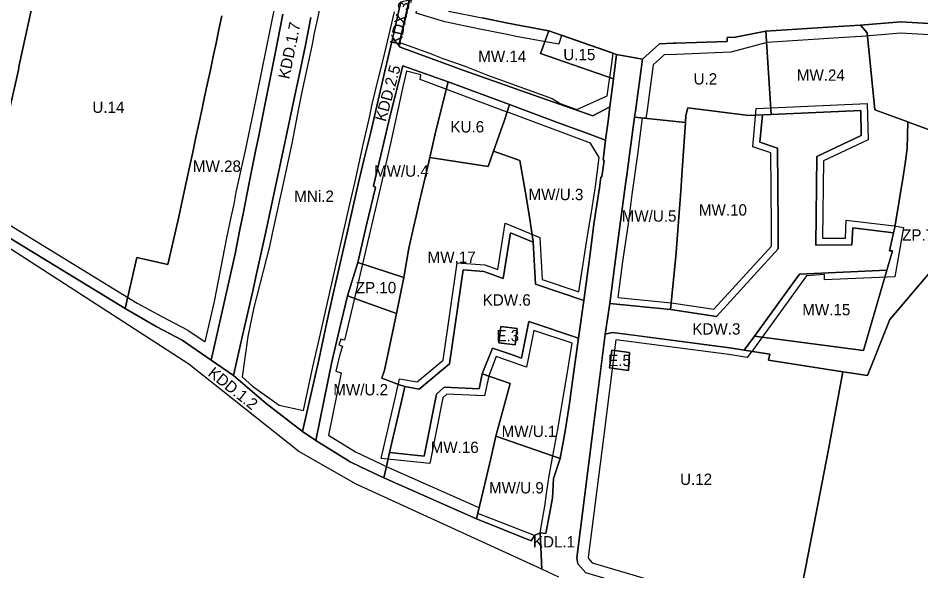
# Model space of a CAD drawing. Extents: x 7421913 to 7423341, y 5550123 to 5551175.
# Drawn here: x 7422221.1 to 7422618.9, y 5550484.1 to 5550727.7 of the extents above; entities that cross this region are included whole.
import ezdxf

# ---------------------------------------------------------------- set-up
doc = ezdxf.new("R2010")
doc.units = 0
for name, color, linetype in [('linie_rozgraniczajace', 7, 'Continuous'), ('linie_zabudowy_nieprzekraczalne', 7, 'Continuous'), ('oznaczenia_przeznaczen', 7, 'Continuous')]:
    doc.layers.add(name, color=color, linetype=linetype)

msp = doc.modelspace()

# ---------------------------------------------------------------- linework, layer by layer
at = {"layer": 'linie_rozgraniczajace'}
for points in [[(7422213.4, 5550774.82), (7422235.34, 5550770.25), (7422234.28, 5550765.52), (7422232.46, 5550757.03), (7422231.35, 5550751.91), (7422231.24, 5550751.35), (7422230.09, 5550746.05), (7422225.78, 5550726.41), (7422221.66, 5550706.89), (7422221.26, 5550704.88), (7422221.11, 5550704.1), (7422217.38, 5550687.41)], [(7422217.38, 5550687.41), (7422221.11, 5550704.1), (7422221.26, 5550704.88), (7422221.66, 5550706.89), (7422225.78, 5550726.41), (7422230.09, 5550746.05)], [(7422389.77, 5550734.83), (7422386.06, 5550718.57), (7422382.76, 5550704.3), (7422376.51, 5550677.37), (7422373.65, 5550665.7), (7422371.09, 5550655.25), (7422366.05, 5550633.02), (7422359.94, 5550606.18), (7422357.09, 5550593.63), (7422353.72, 5550577.68), (7422346.5, 5550545.52), (7422330.37, 5550557.92), (7422316.1, 5550570.15), (7422320.06, 5550587.75), (7422324.64, 5550608.16), (7422325.85, 5550613.68), (7422330.21, 5550633.56), (7422339.26, 5550675.47), (7422343.44, 5550695.67), (7422344.92, 5550702.46), (7422347.79, 5550715.72), (7422350.11, 5550727.89)], [(7422337.8, 5550729.42), (7422336.62, 5550723.39), (7422335.42, 5550717.41), (7422334.23, 5550711.43), (7422333.05, 5550705.55), (7422331.88, 5550699.66), (7422330.71, 5550693.78), (7422329.51, 5550687.8), (7422328.34, 5550681.92), (7422327.12, 5550675.83), (7422325.92, 5550669.86), (7422324.59, 5550663.19), (7422323.26, 5550656.52), (7422321.93, 5550649.85), (7422320.4, 5550642.2), (7422318.88, 5550634.56), (7422316.73, 5550623.77), (7422306.14, 5550576.99), (7422293.48, 5550585.69), (7422282.02, 5550591.84), (7422268.25, 5550599.78), (7422273.44, 5550622.18), (7422287.09, 5550619.14), (7422291.99, 5550640.16), (7422293.62, 5550647.79), (7422295.23, 5550655.31), (7422296.65, 5550661.97), (7422298.08, 5550668.67), (7422299.49, 5550675.26), (7422300.75, 5550681.14), (7422302.03, 5550687.09), (7422303.3, 5550693.05), (7422304.58, 5550699.03), (7422305.83, 5550704.89), (7422307.08, 5550710.77), (7422308.33, 5550716.62), (7422309.63, 5550722.69), (7422310.91, 5550728.65)], [(7422350.11, 5550727.89), (7422347.79, 5550715.72), (7422344.92, 5550702.46), (7422343.44, 5550695.67), (7422339.26, 5550675.47), (7422330.21, 5550633.56), (7422325.85, 5550613.68), (7422324.64, 5550608.16), (7422320.06, 5550587.75), (7422316.1, 5550570.15), (7422306.14, 5550576.99), (7422316.73, 5550623.77), (7422318.88, 5550634.56), (7422320.4, 5550642.2), (7422321.93, 5550649.85), (7422323.26, 5550656.52), (7422324.59, 5550663.19), (7422325.92, 5550669.86), (7422327.12, 5550675.83), (7422328.34, 5550681.92), (7422329.51, 5550687.8), (7422330.71, 5550693.78), (7422331.88, 5550699.66), (7422333.05, 5550705.55), (7422334.23, 5550711.43), (7422335.42, 5550717.41), (7422336.62, 5550723.39), (7422337.8, 5550729.42)], [(7422310.91, 5550728.65), (7422309.63, 5550722.69), (7422308.33, 5550716.62), (7422307.08, 5550710.77), (7422305.83, 5550704.89), (7422304.58, 5550699.03), (7422303.3, 5550693.05), (7422302.03, 5550687.09), (7422300.75, 5550681.14), (7422299.49, 5550675.26), (7422298.08, 5550668.67), (7422296.65, 5550661.97), (7422295.23, 5550655.31), (7422293.62, 5550647.79), (7422291.99, 5550640.16), (7422287.09, 5550619.14), (7422273.44, 5550622.18), (7422268.25, 5550599.78), (7422206.25, 5550637.41)], [(7422657.58, 5550723.32), (7422610.06, 5550726.12), (7422592.25, 5550724.59), (7422582.5, 5550723.96), (7422550.53, 5550721.9), (7422537.06, 5550719.28), (7422533.5, 5550719.14), (7422533.57, 5550717.4), (7422510.99, 5550716.7), (7422509.72, 5550716.6), (7422503.77, 5550716.39), (7422496.18, 5550709.62), (7422484.82, 5550711.66), (7422454.96, 5550722.08), (7422442.35, 5550724.39), (7422436.89, 5550725.5), (7422425.59, 5550727.79)], [(7422563.21, 5550461.08), (7422568.23, 5550485.99), (7422578.06, 5550536.87), (7422584.47, 5550571.85), (7422588.7, 5550571.2), (7422595.34, 5550570.19), (7422605.22, 5550594.9), (7422631.08, 5550625.32), (7422629.43, 5550665.34), (7422628.99, 5550676.11), (7422641.87, 5550676.81), (7422655.16, 5550677.53), (7422659.5, 5550677.77), (7422657.58, 5550723.32), (7422660.02, 5550723.17), (7422675.73, 5550722.2), (7422727.72, 5550719.03), (7422764.65, 5550716.87), (7422772.68, 5550712.64), (7422781.79, 5550712.09), (7422793.57, 5550711.53), (7422796.94, 5550709.04), (7422821.9, 5550696.63), (7422859.96, 5550677.58)], [(7422459.45, 5550481.38), (7422451.85, 5550484.87), (7422451.17, 5550500.92), (7422453.71, 5550500.53), (7422456.62, 5550516.15), (7422457.07, 5550524.93), (7422457.15, 5550525.17), (7422459.97, 5550533.62), (7422462.15, 5550545.61), (7422464.03, 5550557.84), (7422465.71, 5550569.95), (7422468.04, 5550586.69), (7422470.33, 5550603.18), (7422472.73, 5550620.5), (7422474.98, 5550637.98), (7422477.24, 5550652.88), (7422477.92, 5550657.54), (7422478.3, 5550657.67), (7422479.33, 5550665.01), (7422478.9, 5550665.29), (7422479.99, 5550673.89), (7422480.53, 5550678.12), (7422481.05, 5550682.23), (7422481.91, 5550688.66), (7422483.54, 5550700.93), (7422484.82, 5550711.66), (7422496.18, 5550709.62), (7422493.14, 5550686.73), (7422492.78, 5550684), (7422489.55, 5550659.67), (7422488.57, 5550653.51), (7422484.86, 5550624.89), (7422481.88, 5550601.86), (7422479.79, 5550588.35), (7422474.1, 5550543.35), (7422467.27, 5550489.79), (7422467.73, 5550487.22), (7422471.23, 5550483.25)], [(7422206.25, 5550637.41), (7422268.25, 5550599.78), (7422282.02, 5550591.84), (7422293.48, 5550585.69), (7422306.14, 5550576.99), (7422316.1, 5550570.15), (7422330.37, 5550557.92), (7422346.5, 5550545.52), (7422352.31, 5550541.48), (7422367.43, 5550532.2), (7422372.05, 5550529.97), (7422382.22, 5550525.06), (7422423.07, 5550507.05), (7422447.26, 5550497.3), (7422448.67, 5550499.71), (7422451.17, 5550500.92), (7422451.85, 5550484.87), (7422370.09, 5550522.34), (7422344.78, 5550536.66), (7422296.34, 5550575.12), (7422153.5, 5550667.39)]]:
    msp.add_lwpolyline(points, dxfattribs=at)
for points in [[(7422388.85, 5550715.6), (7422386.06, 5550718.57), (7422389.77, 5550734.83), (7422393.38, 5550735.82), (7422392.79, 5550733.16), (7422391.17, 5550725.97)], [(7422454.96, 5550722.08), (7422451.28, 5550712.14), (7422483.54, 5550700.93), (7422481.91, 5550688.66), (7422474.43, 5550684.56), (7422444.95, 5550694.93), (7422433.33, 5550699.08), (7422427.58, 5550701.09), (7422417.05, 5550704.79), (7422403.17, 5550709.84), (7422389.47, 5550714.93), (7422388.85, 5550715.6), (7422391.17, 5550725.97), (7422392.79, 5550733.16), (7422393.38, 5550735.82), (7422400.05, 5550733.99), (7422403.89, 5550733.09), (7422411.25, 5550731.36), (7422410.79, 5550730.73), (7422425.59, 5550727.79), (7422436.89, 5550725.5), (7422442.35, 5550724.39)], [(7422657.58, 5550723.32), (7422659.5, 5550677.77), (7422655.16, 5550677.53), (7422641.87, 5550676.81), (7422628.99, 5550676.11), (7422613.4, 5550681.83), (7422613.12, 5550681.94), (7422598.57, 5550687.28), (7422595.2, 5550721.24), (7422592.25, 5550724.59), (7422610.06, 5550726.12)], [(7422483.54, 5550700.93), (7422451.28, 5550712.14), (7422454.96, 5550722.08), (7422484.82, 5550711.66)], [(7422515.17, 5550681.71), (7422492.78, 5550684), (7422493.14, 5550686.73), (7422496.18, 5550709.62), (7422503.77, 5550716.39), (7422509.72, 5550716.6), (7422510.99, 5550716.7), (7422533.57, 5550717.4), (7422533.5, 5550719.14), (7422537.06, 5550719.28), (7422550.53, 5550721.9), (7422552.98, 5550685.22), (7422543.06, 5550684.77), (7422516.29, 5550688.09), (7422515.37, 5550684.7)], [(7422606.84, 5550633.11), (7422588.89, 5550635.23), (7422588.52, 5550627.79), (7422572.58, 5550627.69), (7422573.01, 5550666.63), (7422592.61, 5550675.89), (7422592.38, 5550687), (7422552.98, 5550685.22), (7422550.53, 5550721.9), (7422582.5, 5550723.96), (7422592.25, 5550724.59), (7422595.2, 5550721.24), (7422598.57, 5550687.28), (7422613.12, 5550681.94), (7422612.8, 5550670.22), (7422612.13, 5550664.64), (7422611.31, 5550658.75), (7422607.4, 5550635.57)], [(7422388.85, 5550715.6), (7422389.47, 5550714.93), (7422403.17, 5550709.84), (7422417.05, 5550704.79), (7422427.58, 5550701.09), (7422433.33, 5550699.08), (7422444.95, 5550694.93), (7422474.43, 5550684.56), (7422481.91, 5550688.66), (7422481.05, 5550682.23), (7422480.53, 5550678.12), (7422479.99, 5550673.89), (7422471.75, 5550676.94), (7422460.03, 5550681.28), (7422437.67, 5550689.55), (7422410.68, 5550699.59), (7422390.61, 5550706.71), (7422385.08, 5550684.77), (7422381.64, 5550670.37), (7422377.72, 5550653.73), (7422378.55, 5550653.1), (7422374.65, 5550636.58), (7422370.83, 5550620.03), (7422366.26, 5550605.32), (7422362.68, 5550590.62), (7422359.38, 5550576.14), (7422352.31, 5550541.48), (7422346.5, 5550545.52), (7422353.72, 5550577.68), (7422357.09, 5550593.63), (7422359.94, 5550606.18), (7422366.05, 5550633.02), (7422371.09, 5550655.25), (7422373.65, 5550665.7), (7422376.51, 5550677.37), (7422382.76, 5550704.3), (7422386.06, 5550718.57)], [(7422410.68, 5550699.59), (7422405.23, 5550677.94), (7422402.5, 5550666.19), (7422401.65, 5550662.5), (7422397.73, 5550645.63), (7422396.51, 5550640.41), (7422395.5, 5550636.02), (7422393.97, 5550629.48), (7422393.24, 5550626.33), (7422391.04, 5550613.33), (7422370.83, 5550620.03), (7422374.65, 5550636.58), (7422378.55, 5550653.1), (7422377.72, 5550653.73), (7422381.64, 5550670.37), (7422385.08, 5550684.77), (7422390.61, 5550706.71)], [(7422437.67, 5550689.55), (7422435.41, 5550682.69), (7422430.52, 5550669.08), (7422428.27, 5550662.3), (7422402.5, 5550666.19), (7422405.23, 5550677.94), (7422410.68, 5550699.59)], [(7422472.73, 5550620.5), (7422470.33, 5550603.18), (7422449.08, 5550610.38), (7422448.14, 5550629), (7422448.13, 5550629.26), (7422446.46, 5550639.95), (7422445.17, 5550648.21), (7422442.26, 5550664.95), (7422430.52, 5550669.08), (7422435.41, 5550682.69), (7422437.67, 5550689.55), (7422460.03, 5550681.28), (7422471.75, 5550676.94), (7422479.99, 5550673.89), (7422478.9, 5550665.29), (7422479.33, 5550665.01), (7422478.3, 5550657.67), (7422477.92, 5550657.54), (7422477.24, 5550652.88), (7422474.98, 5550637.98)], [(7422573.01, 5550666.63), (7422572.58, 5550627.69), (7422588.52, 5550627.79), (7422588.89, 5550635.23), (7422606.84, 5550633.11), (7422605.02, 5550625.06), (7422606.35, 5550625.07), (7422603.9, 5550616.58), (7422565.4, 5550614.87), (7422545.56, 5550587.53), (7422541.04, 5550581.37), (7422534.76, 5550582.37), (7422526.77, 5550583.48), (7422483.05, 5550589.17), (7422479.79, 5550588.35), (7422481.88, 5550601.86), (7422508.56, 5550599.25), (7422528.78, 5550596.24), (7422556.03, 5550625.96), (7422556.03, 5550636.08), (7422555.72, 5550670.43), (7422547.99, 5550673.04), (7422549.08, 5550685.04), (7422552.98, 5550685.22), (7422592.38, 5550687), (7422592.61, 5550675.89)], [(7422549.08, 5550685.04), (7422547.99, 5550673.04), (7422555.72, 5550670.43), (7422556.03, 5550636.08), (7422556.03, 5550625.96), (7422528.78, 5550596.24), (7422508.56, 5550599.25), (7422510.86, 5550622.6), (7422513.15, 5550651.44), (7422513.76, 5550660.65), (7422515.17, 5550681.71), (7422515.37, 5550684.7), (7422516.29, 5550688.09), (7422543.06, 5550684.77)], [(7422515.17, 5550681.71), (7422513.76, 5550660.65), (7422513.15, 5550651.44), (7422510.86, 5550622.6), (7422508.56, 5550599.25), (7422481.88, 5550601.86), (7422484.86, 5550624.89), (7422488.57, 5550653.51), (7422489.55, 5550659.67), (7422492.78, 5550684)], [(7422628.99, 5550676.11), (7422629.43, 5550665.34), (7422631.08, 5550625.32), (7422605.22, 5550594.9), (7422595.34, 5550570.19), (7422588.7, 5550571.2), (7422584.47, 5550571.85), (7422551.74, 5550577), (7422552.34, 5550579.58), (7422541.04, 5550581.37), (7422545.56, 5550587.53), (7422593.68, 5550581.23), (7422606.35, 5550625.07), (7422605.02, 5550625.06), (7422607.4, 5550635.57), (7422611.31, 5550658.75), (7422612.13, 5550664.64), (7422612.8, 5550670.22), (7422613.12, 5550681.94), (7422613.4, 5550681.83)], [(7422448.14, 5550629), (7422438.09, 5550633.08), (7422434.88, 5550612.93), (7422426.3, 5550616), (7422417.17, 5550616.7), (7422411.17, 5550575.35), (7422397.86, 5550564.19), (7422391.47, 5550565.29), (7422389.18, 5550566.13), (7422381.34, 5550569.06), (7422382.53, 5550572.51), (7422384.86, 5550583.53), (7422387.8, 5550597.46), (7422391.04, 5550613.33), (7422393.24, 5550626.33), (7422393.97, 5550629.48), (7422395.5, 5550636.02), (7422396.51, 5550640.41), (7422397.73, 5550645.63), (7422401.65, 5550662.5), (7422402.5, 5550666.19), (7422428.27, 5550662.3), (7422430.52, 5550669.08), (7422442.26, 5550664.95), (7422445.17, 5550648.21), (7422446.46, 5550639.95), (7422448.13, 5550629.26)], [(7422448.14, 5550629), (7422449.08, 5550610.38), (7422470.33, 5550603.18), (7422468.04, 5550586.69), (7422446.15, 5550593.94), (7422442.9, 5550577.86), (7422437.67, 5550579.68), (7422435.02, 5550580.59), (7422430.11, 5550582.29), (7422425.62, 5550570.96), (7422424.21, 5550564.38), (7422408.84, 5550565), (7422405.49, 5550561.91), (7422400.09, 5550534.7), (7422384.8, 5550536.27), (7422390.28, 5550560.05), (7422391.47, 5550565.29), (7422397.86, 5550564.19), (7422411.17, 5550575.35), (7422417.17, 5550616.7), (7422426.3, 5550616), (7422434.88, 5550612.93), (7422438.09, 5550633.08)], [(7422391.04, 5550613.33), (7422387.8, 5550597.46), (7422376.42, 5550601.61), (7422366.26, 5550605.32), (7422370.83, 5550620.03)], [(7422565.4, 5550614.87), (7422603.9, 5550616.58), (7422593.68, 5550581.23), (7422545.56, 5550587.53)], [(7422383.69, 5550531.45), (7422382.22, 5550525.06), (7422372.05, 5550529.97), (7422367.43, 5550532.2), (7422352.31, 5550541.48), (7422359.38, 5550576.14), (7422362.68, 5550590.62), (7422366.26, 5550605.32), (7422376.42, 5550601.61), (7422387.8, 5550597.46), (7422384.86, 5550583.53), (7422382.53, 5550572.51), (7422381.35, 5550569.09), (7422381.34, 5550569.06), (7422389.18, 5550566.13), (7422391.47, 5550565.29), (7422390.28, 5550560.05), (7422384.8, 5550536.27)], [(7422459.97, 5550533.62), (7422431.61, 5550543.48), (7422434.74, 5550554.74), (7422437.93, 5550566.65), (7422425.62, 5550570.96), (7422430.11, 5550582.29), (7422435.02, 5550580.59), (7422437.67, 5550579.68), (7422442.9, 5550577.86), (7422446.15, 5550593.94), (7422468.04, 5550586.69), (7422465.71, 5550569.95), (7422464.03, 5550557.84), (7422462.15, 5550545.61)], [(7422440.72, 5550588.8), (7422440.08, 5550583.71), (7422432.95, 5550584.62), (7422433.85, 5550591.73), (7422440.98, 5550590.83)], [(7422440.72, 5550588.8), (7422440.98, 5550590.83), (7422433.85, 5550591.73), (7422432.95, 5550584.62), (7422440.08, 5550583.71)], [(7422541.04, 5550581.37), (7422552.34, 5550579.58), (7422551.74, 5550577), (7422584.47, 5550571.85), (7422578.06, 5550536.87), (7422568.23, 5550485.99), (7422563.21, 5550461.08), (7422562.27, 5550456.27), (7422525.39, 5550467.23), (7422471.23, 5550483.25), (7422467.73, 5550487.22), (7422467.27, 5550489.79), (7422474.1, 5550543.35), (7422478.15, 5550575.36), (7422479.79, 5550588.35), (7422483.05, 5550589.17), (7422492.4, 5550587.95), (7422526.77, 5550583.48), (7422534.76, 5550582.37)], [(7422481.73, 5550573.52), (7422490.08, 5550572.37), (7422490.48, 5550580.26), (7422482.66, 5550581.34)], [(7422490.48, 5550580.26), (7422490.08, 5550572.37), (7422481.73, 5550573.52), (7422482.66, 5550581.34)], [(7422384.8, 5550536.27), (7422400.09, 5550534.7), (7422405.49, 5550561.91), (7422408.84, 5550565), (7422424.21, 5550564.38), (7422425.62, 5550570.96), (7422437.93, 5550566.65), (7422434.74, 5550554.74), (7422431.61, 5550543.48), (7422429.37, 5550533.61), (7422427.53, 5550525.53), (7422423.07, 5550507.05), (7422382.22, 5550525.06), (7422383.69, 5550531.45)], [(7422459.97, 5550533.62), (7422457.15, 5550525.17), (7422457.07, 5550524.93), (7422456.62, 5550516.15), (7422453.71, 5550500.53), (7422451.17, 5550500.92), (7422448.67, 5550499.71), (7422447.26, 5550497.3), (7422423.07, 5550507.05), (7422427.53, 5550525.53), (7422429.37, 5550533.61), (7422431.61, 5550543.48)]]:
    msp.add_lwpolyline(points, close=True, dxfattribs=at)
at = {"layer": 'linie_zabudowy_nieprzekraczalne'}
for points in [[(7422208.84, 5550641.68), (7422273.52, 5550602.11), (7422284.45, 5550596.21), (7422295.84, 5550590.1), (7422295.98, 5550590.02), (7422296.26, 5550589.85), (7422296.31, 5550589.81), (7422303.54, 5550585.05), (7422307.64, 5550602.85), (7422313.14, 5550630.91), (7422315.01, 5550639.96), (7422316.31, 5550645.74), (7422317.24, 5550651.05), (7422321.62, 5550670.63), (7422322.18, 5550673.61), (7422324.14, 5550682.75), (7422324.7, 5550685.55), (7422336.17, 5550742.05)], [(7422354.76, 5550736.26), (7422352.98, 5550727.49), (7422351.49, 5550720.41), (7422351.31, 5550719.29), (7422350.56, 5550715.47), (7422349.63, 5550711.36), (7422346.09, 5550695.23), (7422344.69, 5550687.87), (7422341.8, 5550672.39), (7422338.44, 5550657.48), (7422333.13, 5550632.77), (7422331.82, 5550627.08), (7422325.02, 5550600.23), (7422322.41, 5550587.37), (7422319.79, 5550569.65), (7422324.46, 5550565.46), (7422336.11, 5550557.07), (7422346.92, 5550554.74), (7422350.93, 5550573.94), (7422354.29, 5550588.02), (7422361.94, 5550622.42), (7422367.34, 5550645.64), (7422369.58, 5550655.7), (7422373.22, 5550671.93), (7422376.01, 5550683.86), (7422377.13, 5550689.73), (7422379.74, 5550700.64), (7422382.17, 5550709.87), (7422387.01, 5550730.48)], [(7422397.31, 5550734.1), (7422393.4, 5550734.85), (7422389.39, 5550716.95), (7422402.44, 5550712.28), (7422408.31, 5550709.95), (7422417.64, 5550706.69), (7422427.89, 5550702.59), (7422456.51, 5550692.24), (7422459.96, 5550690), (7422467.33, 5550687.39), (7422480.75, 5550693.45), (7422482.8, 5550707.62), (7422483.27, 5550712.28), (7422460.61, 5550720.12), (7422459.4, 5550716.2), (7422441.37, 5550719.49), (7422441.35, 5550719.49), (7422435.9, 5550720.6), (7422424.61, 5550722.89), (7422409.18, 5550726), (7422396.47, 5550729.81), (7422397.4, 5550734.29)], [(7422657.28, 5550718.33), (7422610.13, 5550721.11), (7422592.68, 5550719.61), (7422592.58, 5550719.6), (7422592.57, 5550719.6), (7422582.82, 5550718.97), (7422551.17, 5550716.93), (7422535.18, 5550712.67), (7422511.26, 5550711.71), (7422505.75, 5550711.46), (7422500.89, 5550707.12), (7422498.1, 5550686.07), (7422497.71, 5550683.56), (7422496.09, 5550683.77), (7422494.04, 5550667.62), (7422491.58, 5550649.94), (7422490, 5550637.04), (7422487.43, 5550620.37), (7422485.39, 5550604.58), (7422508.85, 5550602.24), (7422508.95, 5550602.22), (7422509, 5550602.22), (7422527.65, 5550599.44), (7422553.03, 5550627.13), (7422553.03, 5550636.07), (7422552.74, 5550668.27), (7422544.8, 5550670.96), (7422546.31, 5550687.88), (7422552.84, 5550688.22), (7422595.29, 5550690.13), (7422595.66, 5550674.03), (7422575.99, 5550664.72), (7422575.62, 5550630.71), (7422585.67, 5550630.78), (7422586.04, 5550638.61), (7422607.19, 5550636.09), (7422607.23, 5550636.08), (7422607.43, 5550636.05), (7422607.49, 5550636.04)], [(7422436.6, 5550686.29), (7422398.33, 5550700.59), (7422398.61, 5550702.76), (7422392.31, 5550704.37), (7422390.7, 5550697.44), (7422385.18, 5550672.48), (7422380.71, 5550652.55), (7422372.89, 5550619.35), (7422369.32, 5550604.2)], [(7422369.32, 5550604.2), (7422364.97, 5550585.78), (7422363.3, 5550586.27), (7422362.39, 5550583.75), (7422364.06, 5550583.19), (7422362.95, 5550579.48), (7422361.06, 5550572.14), (7422363.5, 5550571.37), (7422357.91, 5550543.91), (7422369.83, 5550536.59), (7422384.32, 5550529.6), (7422424.2, 5550512.08), (7422423.58, 5550509.52), (7422448.53, 5550499.77), (7422451.12, 5550500.89), (7422453.29, 5550513.48), (7422453.78, 5550517.11), (7422455.17, 5550525.92), (7422456.78, 5550534.8), (7422458.95, 5550546.55), (7422463.08, 5550570.74), (7422465.31, 5550584.45), (7422448.42, 5550590.03), (7422445.17, 5550573.92), (7422436.69, 5550576.84), (7422434.05, 5550577.75), (7422434.04, 5550577.76), (7422431.84, 5550578.52), (7422428.5, 5550570.09), (7422426.63, 5550561.29), (7422409.96, 5550561.96), (7422408.25, 5550560.37), (7422402.48, 5550531.44), (7422381.12, 5550533.64), (7422387.36, 5550560.72), (7422389.17, 5550568.72), (7422397, 5550567.39), (7422408.37, 5550576.91), (7422414.62, 5550619.9), (7422426.83, 5550618.98), (7422432.49, 5550616.97), (7422435.71, 5550637.27), (7422451.05, 5550631.05), (7422451.97, 5550612.57), (7422468.22, 5550607.05), (7422471.63, 5550628.98), (7422474.14, 5550644.08), (7422475.57, 5550653.46), (7422477.09, 5550666.31), (7422473.36, 5550672.55), (7422436.44, 5550686.35)], [(7422607.23, 5550636.08), (7422611.21, 5550635.4), (7422607.39, 5550613.61), (7422576.43, 5550612.38), (7422576.43, 5550614.69), (7422568.53, 5550614.14), (7422544.38, 5550580.84)], [(7422544.46, 5550580.96), (7422542.41, 5550578.12), (7422534.32, 5550579.4), (7422526.37, 5550580.51), (7422484.53, 5550585.95), (7422479.06, 5550542.72), (7422479.06, 5550542.72), (7422472.33, 5550489.92), (7422472.41, 5550489.48), (7422474.03, 5550487.64), (7422526.81, 5550472.02), (7422526.81, 5550472.02), (7422565.2, 5550460.62), (7422573.85, 5550449.15), (7422617.82, 5550425.41), (7422614.79, 5550419.46)]]:
    msp.add_lwpolyline(points, dxfattribs=at)

# ---------------------------------------------------------------- texts
at = {"layer": 'oznaczenia_przeznaczen'}
for s, rotation, p in [('KDX.3', 77.5331, (7422389.65, 5550715.42)), ('KDD.1.7', 78.453, (7422340.59, 5550700.56)), ('KDD.2.5', 74.6884, (7422383.1, 5550681.77)), ('KDD.1.2', 321.5409, (7422304.4, 5550570.45))]:
    msp.add_text(s, height=5, rotation=rotation, dxfattribs=at).set_placement(p)
for s, p in [('MW.14', (7422423.84, 5550708.28)), ('U.15', (7422461.35, 5550709.14)), ('MW.24', (7422564.24, 5550700.05)), ('U.2', (7422518.75, 5550698.41)), ('U.14', (7422253.85, 5550685.93)), ('KU.6', (7422411.6, 5550677.29)), ('MW.28', (7422298.14, 5550659.94)), ('MW/U.4', (7422377.94, 5550657.8)), ('MNi.2', (7422342.8, 5550646.71)), ('MW/U.3', (7422446.03, 5550647.46)), ('MW.10', (7422521.08, 5550640.65)), ('MW/U.5', (7422487.07, 5550637.98)), ('ZP.7', (7422610.63, 5550629.59)), ('MW.17', (7422401.55, 5550619.83)), ('ZP.10', (7422369.89, 5550606.42)), ('KDW.6', (7422425.84, 5550600.98)), ('MW.15', (7422566.64, 5550596.72)), ('E.3', (7422431.87, 5550585.22)), ('KDW.3', (7422518.21, 5550588.22)), ('E.5', (7422481.1, 5550574.33)), ('MW/U.2', (7422359.99, 5550561.43)), ('MW/U.1', (7422434.17, 5550543.08)), ('MW.16', (7422402.9, 5550536.05)), ('U.12', (7422512.79, 5550521.97)), ('MW/U.9', (7422428.62, 5550518.21)), ('KDL.1', (7422447.96, 5550494.42))]:
    msp.add_text(s, height=5, dxfattribs=at).set_placement(p)

doc.saveas('drawing.dxf')
